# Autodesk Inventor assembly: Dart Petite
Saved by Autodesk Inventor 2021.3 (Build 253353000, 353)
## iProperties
Created: 2022-09
Part Number: Dart Petite
Document SubType Name: Assembly
Designer: Administrator
Title: Dart Petite v6
Author: Administrator
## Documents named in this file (3)
- c:\worker\convert-fusion-r05\tmp\job-1\2317\output\files\3a42743e-2115-4501-be9e-893302b51704\3f33dea5-3133-4f02-b3ae-08ad683733a0.iam
- c:\worker\convert-fusion-r05\tmp\job-1\2317\output\files\3a42743e-2115-4501-be9e-893302b51704\Dart Petite.ipt
- c:\worker\convert-fusion-r05\tmp\job-1\2317\output\files\3a42743e-2115-4501-be9e-893302b51704\Part4.ipt
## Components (2 placed, 2 different names)
1. Dart Petite:1
2. Part4
